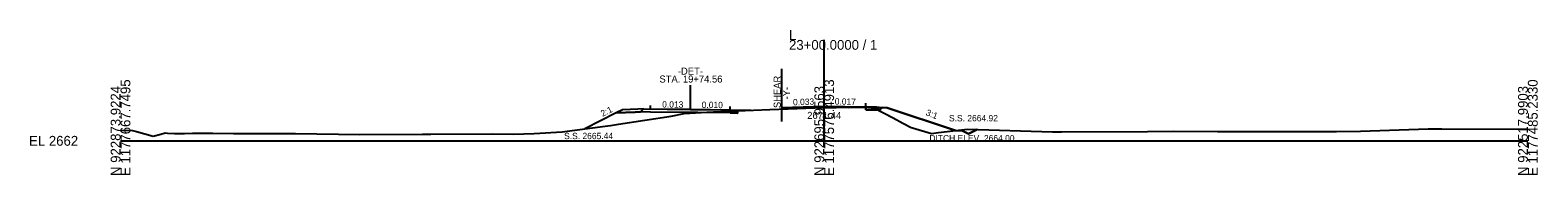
# Model space of a CAD drawing. Extents: x -26 to 1403, y -10 to 9563.
# Drawn here: x 974.3 to 1402.8, y 2990.3 to 3031.5 of the extents above; entities that cross this region are included whole.
import ezdxf

# ---------------------------------------------------------------- set-up
doc = ezdxf.new("R2010")
doc.units = 0
for name, color, linetype in [('Exist Cross Section Cell', 7, 'Continuous'), ('Exist XS Center Line Elevation Label', 7, 'Continuous'), ('Exist XS Ground Line', 7, 'Continuous'), ('Prop XS DDE Earthwork Shape', 7, 'Continuous'), ('Prop XS Ditch Standard Text', 7, 'Continuous'), ('Prop XS Dump Level', 7, 'Continuous'), ('Prop XS Earthwork Shape', 7, 'Continuous'), ('Prop XS EOT Tick Mark', 7, 'Continuous'), ('Prop XS Finish Grade', 7, 'Continuous'), ('Prop XS Finish Grade Earthwork', 7, 'Continuous'), ('Prop XS Finish Grade Paved Shoulder', 7, 'Continuous'), ('Prop XS Finish Grade Pavement', 7, 'Continuous'), ('Prop XS Pvmt Edge Slope', 7, 'Continuous'), ('Prop XS SE Text', 7, 'Continuous'), ('Prop XS Shoulder Borrow Shape', 7, 'Continuous'), ('Prop XS Side Slope Text', 7, 'Continuous'), ('Prop XS SS Elevation Text', 7, 'Continuous'), ('Prop XS Subgrade Earthwork', 7, 'Continuous'), ('Prop XS Vertical Lines', 7, 'Continuous'), ('Prop XS Wedging', 7, 'Continuous')]:
    doc.layers.add(name, color=color, linetype=linetype)

msp = doc.modelspace()

# ---------------------------------------------------------------- linework, layer by layer
at = {"layer": 'Exist Cross Section Cell'}
for p, q in [((1200, 3000), (1200, 3028.71)), ((1000, 3000), (1200, 3000)), ((1200, 3000), (1400, 3000))]:
    msp.add_line(p, q, dxfattribs=at)
at = {"layer": 'Exist XS Ground Line'}
for p, q in [((1168.5, 3008.28), (1170.64, 3008.36)), ((1170.64, 3008.36), (1184.53, 3008.91)), ((1184.53, 3008.91), (1189.74, 3009.06)), ((1189.74, 3009.06), (1199.91, 3009.44)), ((1199.91, 3009.44), (1203.39, 3009.48)), ((1203.39, 3009.48), (1211.47, 3009.57)), ((1211.47, 3009.57), (1213.31, 3009.42)), ((1213.31, 3009.42), (1214.15, 3009.38)), ((1214.15, 3009.38), (1219.59, 3006.52)), ((1125.54, 3002.58), (1137.76, 3004.22)), ((1137.76, 3004.22), (1139.22, 3004.33)), ((1139.22, 3004.33), (1141.58, 3004.76)), ((1141.58, 3004.76), (1156.46, 3007.06)), ((1156.46, 3007.06), (1160.24, 3007.81)), ((1160.24, 3007.81), (1166.61, 3008.18)), ((1166.61, 3008.18), (1168.5, 3008.28)), ((1219.59, 3006.52), (1222.39, 3005.01)), ((1222.39, 3005.01), (1224.71, 3003.76)), ((1000, 3003.02), (1003.38, 3002.92)), ((1003.38, 3002.92), (1004.53, 3002.62)), ((1004.53, 3002.62), (1009.26, 3001.3)), ((1009.26, 3001.3), (1011.48, 3001.87)), ((1011.48, 3001.87), (1012.68, 3002.25)), ((1012.68, 3002.25), (1013.35, 3002.21)), ((1013.35, 3002.21), (1015.29, 3002.11)), ((1015.29, 3002.11), (1018.15, 3002.11)), ((1018.15, 3002.11), (1020.44, 3002.2)), ((1020.44, 3002.2), (1026.2, 3002.14)), ((1026.2, 3002.14), (1032.13, 3002.07)), ((1032.13, 3002.07), (1047.39, 3002.05)), ((1047.39, 3002.05), (1049.12, 3002.06)), ((1049.12, 3002.06), (1049.68, 3002.06)), ((1049.68, 3002.06), (1068.02, 3001.84)), ((1068.02, 3001.84), (1085.81, 3001.92)), ((1085.81, 3001.92), (1086.72, 3001.93)), ((1086.72, 3001.93), (1088.22, 3001.93)), ((1088.22, 3001.93), (1105.86, 3001.97)), ((1105.86, 3001.97), (1111.68, 3001.91)), ((1111.68, 3001.91), (1117.52, 3002.08)), ((1117.52, 3002.08), (1125.54, 3002.58)), ((1224.71, 3003.76), (1225.07, 3003.67)), ((1225.07, 3003.67), (1230.47, 3002.11)), ((1230.47, 3002.11), (1232.48, 3002.35)), ((1232.48, 3002.35), (1240.7, 3003.33)), ((1240.7, 3003.33), (1264.91, 3002.56)), ((1264.91, 3002.56), (1265.36, 3002.54)), ((1265.36, 3002.54), (1265.71, 3002.54)), ((1265.71, 3002.54), (1267.47, 3002.55)), ((1267.47, 3002.55), (1291.85, 3002.65)), ((1291.85, 3002.65), (1299.23, 3002.74)), ((1299.23, 3002.74), (1311.77, 3002.65)), ((1311.77, 3002.65), (1319.54, 3002.64)), ((1319.54, 3002.64), (1333.97, 3002.63)), ((1333.97, 3002.63), (1345.57, 3002.68)), ((1345.57, 3002.68), (1352.43, 3002.79)), ((1352.43, 3002.79), (1368.94, 3003.34)), ((1368.94, 3003.34), (1371.71, 3003.41)), ((1371.71, 3003.41), (1372.67, 3003.42)), ((1372.67, 3003.42), (1375.52, 3003.41)), ((1375.52, 3003.41), (1398.52, 3003.28)), ((1398.52, 3003.28), (1400, 3003.28))]:
    msp.add_line(p, q, dxfattribs=at)
at = {"layer": 'Prop XS DDE Earthwork Shape'}
msp.add_lwpolyline([(1237.28, 3002.92), (1240.7, 3003.33), (1243.52, 3003.24), (1241.04, 3002), (1239.28, 3002.88)], close=True, dxfattribs=at)
at = {"layer": 'Prop XS Dump Level'}
for p, q in [((1148.63, 3009.06), (1161.97, 3008.88)), ((1161.97, 3008.88), (1150.63, 3009.03)), ((1173.31, 3008.76), (1161.97, 3008.88)), ((1161.97, 3008.88), (1179.22, 3008.7)), ((1188, 3009.48), (1200, 3009.88)), ((1200, 3009.88), (1211.88, 3009.69))]:
    msp.add_line(p, q, dxfattribs=at)
at = {"layer": 'Prop XS Earthwork Shape'}
for p, q in [((1213.31, 3009.42), (1211.88, 3009.54)), ((1211.88, 3009.54), (1211.88, 3008.85)), ((1211.88, 3008.85), (1215.28, 3008.79)), ((1214.15, 3009.38), (1213.31, 3009.42)), ((1215.28, 3008.79), (1214.15, 3009.38)), ((1215.73, 3008.78), (1215.28, 3008.79)), ((1215.28, 3008.79), (1219.59, 3006.52)), ((1216.46, 3009.5), (1215.73, 3008.78)), ((1217.88, 3009.39), (1216.46, 3009.5)), ((1237.28, 3002.92), (1217.88, 3009.39)), ((1140.9, 3007.92), (1131.95, 3003.44)), ((1131.95, 3003.44), (1137.76, 3004.22)), ((1137.76, 3004.22), (1139.22, 3004.33)), ((1139.22, 3004.33), (1141.58, 3004.76)), ((1146.24, 3008.16), (1140.9, 3007.92)), ((1141.58, 3004.76), (1156.46, 3007.06)), ((1147.81, 3008.24), (1146.24, 3008.16)), ((1150.63, 3008.2), (1147.81, 3008.24)), ((1161.97, 3008.05), (1150.63, 3008.2)), ((1156.46, 3007.06), (1160.24, 3007.81)), ((1160.24, 3007.81), (1164.02, 3008.03)), ((1164.02, 3008.03), (1161.97, 3008.05)), ((1219.59, 3006.52), (1222.39, 3005.01)), ((1222.39, 3005.01), (1224.71, 3003.76)), ((1224.71, 3003.76), (1225.07, 3003.67)), ((1225.07, 3003.67), (1230.47, 3002.11)), ((1230.47, 3002.11), (1232.48, 3002.35)), ((1232.48, 3002.35), (1237.28, 3002.92))]:
    msp.add_line(p, q, dxfattribs=at)
msp.add_lwpolyline([(1164.06, 3008.03), (1166.61, 3008.18), (1168.5, 3008.28), (1170.64, 3008.36), (1175.31, 3008.55), (1175.31, 3007.91), (1173.31, 3007.93)], close=True, dxfattribs=at)
at = {"layer": 'Prop XS EOT Tick Mark'}
for p, q in [((1150.63, 3009.03), (1150.63, 3010.03)), ((1173.31, 3008.76), (1173.31, 3009.76)), ((1188, 3009.48), (1188, 3010.48)), ((1211.88, 3009.69), (1211.88, 3010.69))]:
    msp.add_line(p, q, dxfattribs=at)
at = {"layer": 'Prop XS Finish Grade'}
for p, q in [((1148.63, 3009.06), (1147.06, 3008.99)), ((1188, 3009.48), (1188, 3009.01)), ((1214.88, 3009.63), (1216.46, 3009.5))]:
    msp.add_line(p, q, dxfattribs=at)
at = {"layer": 'Prop XS Finish Grade Earthwork'}
for p, q in [((1142.63, 3008.78), (1140.9, 3007.92)), ((1147.06, 3008.99), (1142.63, 3008.78)), ((1216.46, 3009.5), (1217.88, 3009.39)), ((1217.88, 3009.39), (1237.28, 3002.92)), ((1140.9, 3007.92), (1131.95, 3003.44)), ((1237.28, 3002.92), (1239.28, 3002.88)), ((1239.28, 3002.88), (1241.04, 3002)), ((1241.04, 3002), (1243.52, 3003.24))]:
    msp.add_line(p, q, dxfattribs=at)
at = {"layer": 'Prop XS Finish Grade Paved Shoulder'}
msp.add_line((1211.88, 3009.69), (1214.88, 3009.63), dxfattribs=at)
at = {"layer": 'Prop XS Finish Grade Pavement'}
for p, q in [((1148.63, 3009.06), (1161.97, 3008.88)), ((1161.97, 3008.88), (1179.22, 3008.7)), ((1188, 3009.48), (1200, 3009.88)), ((1200, 3009.88), (1211.88, 3009.69))]:
    msp.add_line(p, q, dxfattribs=at)
at = {"layer": 'Prop XS Pvmt Edge Slope'}
for p, q in [((1148.63, 3009.06), (1147.81, 3008.24)), ((1214.88, 3009.63), (1215.73, 3008.78))]:
    msp.add_line(p, q, dxfattribs=at)
at = {"layer": 'Prop XS Shoulder Borrow Shape'}
for p, q in [((1142.63, 3008.78), (1140.9, 3007.92)), ((1147.06, 3008.99), (1142.63, 3008.78)), ((1148.63, 3009.06), (1147.06, 3008.99)), ((1147.81, 3008.24), (1148.63, 3009.06)), ((1140.9, 3007.92), (1146.24, 3008.16)), ((1146.24, 3008.16), (1147.81, 3008.24))]:
    msp.add_line(p, q, dxfattribs=at)
at = {"layer": 'Prop XS Subgrade Earthwork'}
for p, q in [((1175.31, 3007.91), (1175.31, 3008.55)), ((1188, 3008.66), (1188, 3009.01)), ((1211.88, 3008.85), (1211.88, 3009.54)), ((1211.88, 3008.85), (1215.73, 3008.78)), ((1215.73, 3008.78), (1216.46, 3009.5)), ((1146.24, 3008.16), (1140.9, 3007.92)), ((1147.81, 3008.24), (1146.24, 3008.16)), ((1150.63, 3008.2), (1147.81, 3008.24)), ((1161.97, 3008.05), (1150.63, 3008.2)), ((1173.31, 3007.93), (1161.97, 3008.05)), ((1173.31, 3007.93), (1175.31, 3007.91))]:
    msp.add_line(p, q, dxfattribs=at)
at = {"layer": 'Prop XS Vertical Lines'}
for p, q in [((1188, 3005.5), (1188, 3020.5)), ((1161.97, 3008.88), (1161.97, 3015.88))]:
    msp.add_line(p, q, dxfattribs=at)
at = {"layer": 'Prop XS Wedging'}
for points in [[(1189.74, 3009.06), (1189.74, 3009.29), (1199.91, 3009.63), (1200, 3009.63), (1203.39, 3009.58), (1206.99, 3009.52), (1206.99, 3009.52), (1203.39, 3009.48), (1200, 3009.44), (1199.91, 3009.44)], [(1189.74, 3009.06), (1189.74, 3009.29), (1199.91, 3009.63), (1200, 3009.63), (1200.13, 3009.63), (1200.31, 3009.45), (1200, 3009.44), (1199.91, 3009.44)]]:
    msp.add_lwpolyline(points, close=True, dxfattribs=at)

# ---------------------------------------------------------------- texts
at = {"layer": 'Exist Cross Section Cell'}
for s, p in [('L', (1190, 3028.71)), ('23+00.0000 / 1', (1190, 3025.91)), ('EL 2662', (974, 2998.6))]:
    msp.add_text(s, height=2.8, dxfattribs=at).set_placement(p)
for s, p in [('E 1177667.7495', (1002.8, 2990)), ('E 1177576.4913', (1202.8, 2990)), ('E 1177485.2330', (1402.8, 2990)), ('N 922873.9224', (1000, 2990)), ('N 922695.9563', (1200, 2990)), ('N 922517.9903', (1400, 2990))]:
    msp.add_text(s, height=2.8, rotation=90, dxfattribs=at).set_placement(p)
at = {"layer": 'Exist XS Center Line Elevation Label'}
msp.add_text('2671.44', height=2, dxfattribs=at).set_placement((1195.17, 3006.24))
at = {"layer": 'Prop XS Ditch Standard Text'}
msp.add_text('DITCH ELEV. 2664.00', height=1.8, dxfattribs=at).set_placement((1229.89, 2999.84))
at = {"layer": 'Prop XS Dump Level'}
msp.add_text('Case1', height=0.04, dxfattribs=at).set_placement((1142.63, 3008.62))
at = {"layer": 'Prop XS SE Text'}
for s, rotation, p in [('0.013', 359.2327, (1153.93, 3009.49)), ('0.010', 359.3991, (1165.17, 3009.35)), ('0.033', 1.9092, (1191.16, 3010.09)), ('0.017', 359.0452, (1202.98, 3010.33))]:
    msp.add_text(s, height=1.8, rotation=rotation, dxfattribs=at).set_placement(p)
at = {"layer": 'Prop XS Side Slope Text'}
for s, rotation, p in [('2:1', 26.5651, (1137.03, 3006.81)), ('3:1', 338.4796, (1228.73, 3007.35))]:
    msp.add_text(s, height=1.8, rotation=rotation, dxfattribs=at).set_placement(p)
at = {"layer": 'Prop XS SS Elevation Text'}
for s, p in [('S.S. 2664.92', (1235.46, 3005.54)), ('S.S. 2665.44', (1126.07, 3000.48))]:
    msp.add_text(s, height=1.8, dxfattribs=at).set_placement(p)
at = {"layer": 'Prop XS Vertical Lines'}
for s, p in [('STA. 19+74.56', (1153.16, 3016.59)), ('-DET-', (1158.41, 3018.84))]:
    msp.add_text(s, height=2, dxfattribs=at).set_placement(p)
for s, p in [('SHEAR', (1187.63, 3009.31)), ('-Y-', (1190.25, 3011.77))]:
    msp.add_text(s, height=2, rotation=90, dxfattribs=at).set_placement(p)

doc.saveas('drawing.dxf')
